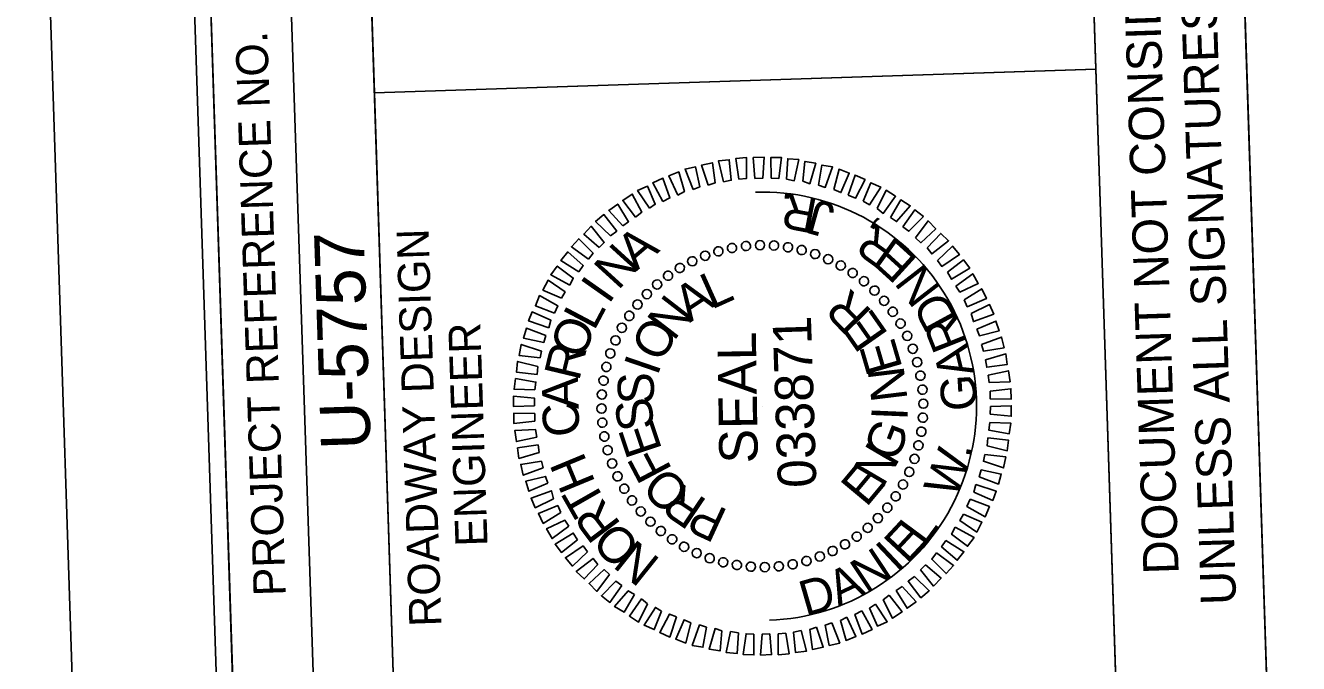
# Model space of a CAD drawing. Extents: x 1627314 to 1628469, y 762309 to 764230.
# Drawn here: x 1627314.2 to 1627512.6, y 763788.2 to 763887.6 of the extents above; entities that cross this region are included whole.
import ezdxf

# ---------------------------------------------------------------- set-up
doc = ezdxf.new("R2010")
doc.units = 0
for name, color, linetype in [('Old_Level_2', 7, 'Continuous'), ('Scratch_Level_0', 7, 'Continuous'), ('Sheet Data Field CELL', 7, 'Continuous'), ('Sheet Plot Border Inside CELL', 7, 'Continuous'), ('Sheet Plot Border Outside CELL', 7, 'Continuous'), ('Sheet Professional Seal CELL', 7, 'Continuous'), ('Sheet Profile CELL', 7, 'Continuous'), ('Sheet Profile Grid Major CELL', 7, 'Continuous'), ('Sheet Profile Grid Minor CELL', 7, 'Continuous'), ('Sheet Sticker Exception Certification CELL', 7, 'Continuous')]:
    doc.layers.add(name, color=color, linetype=linetype)

msp = doc.modelspace()

# ---------------------------------------------------------------- linework, layer by layer
at = {"layer": 'Old_Level_2'}
msp.add_lwpolyline([(1627507.79, 763781.61), (1627501.25, 763981.49), (1627565.16, 763983.58), (1627571.7, 763783.7)], close=True, dxfattribs=at)
at = {"layer": 'Scratch_Level_0'}
msp.add_arc((1627429.07, 763828.3), 33.36, 271.8735, 91.8735, dxfattribs=at)
at = {"layer": 'Sheet Plot Border Inside CELL'}
msp.add_lwpolyline([(1628446.34, 762357.53), (1628391.86, 764023.14), (1627337.33, 763988.65), (1627391.81, 762323.04)], close=True, dxfattribs=at)
at = {"layer": 'Sheet Plot Border Outside CELL'}
msp.add_lwpolyline([(1628469.21, 762345.27), (1628413.63, 764044.37), (1627314.22, 764008.4), (1627369.79, 762309.31)], close=True, dxfattribs=at)
at = {"layer": 'Sheet Professional Seal CELL'}
for p, q in [((1627422.18, 763852.44), (1627422.18, 763852.44)), ((1627424.36, 763852.91), (1627424.36, 763852.91)), ((1627426.5, 763853.28), (1627426.5, 763853.28)), ((1627428.7, 763853.4), (1627428.7, 763853.4)), ((1627430.9, 763853.32), (1627430.9, 763853.32)), ((1627433.06, 763853.04), (1627433.06, 763853.04)), ((1627435.18, 763852.66), (1627435.18, 763852.66)), ((1627418.13, 763850.9), (1627418.13, 763850.9)), ((1627420.1, 763851.77), (1627420.1, 763851.77)), ((1627437.3, 763852.03), (1627437.3, 763852.03)), ((1627439.33, 763851.2), (1627439.33, 763851.2)), ((1627441.31, 763850.26), (1627441.31, 763850.26)), ((1627414.35, 763848.63), (1627414.35, 763848.63)), ((1627416.21, 763849.84), (1627416.21, 763849.84)), ((1627443.15, 763849.07), (1627443.15, 763849.07)), ((1627412.64, 763847.32), (1627412.64, 763847.32)), ((1627444.94, 763847.78), (1627444.94, 763847.78)), ((1627446.54, 763846.33), (1627446.54, 763846.33)), ((1627411.04, 763845.77), (1627411.04, 763845.77)), ((1627448.09, 763844.73), (1627448.09, 763844.73)), ((1627408.3, 763842.38), (1627408.3, 763842.38)), ((1627409.59, 763844.17), (1627409.59, 763844.17)), ((1627449.4, 763843.02), (1627449.4, 763843.02)), ((1627407.11, 763840.54), (1627407.11, 763840.54)), ((1627450.61, 763841.16), (1627450.61, 763841.16)), ((1627406.17, 763838.56), (1627406.17, 763838.56)), ((1627451.67, 763839.25), (1627451.67, 763839.25)), ((1627405.34, 763836.53), (1627405.34, 763836.53)), ((1627452.54, 763837.27), (1627452.54, 763837.27)), ((1627404.71, 763834.41), (1627404.71, 763834.41)), ((1627453.21, 763835.19), (1627453.21, 763835.19)), ((1627453.68, 763833.01), (1627453.68, 763833.01)), ((1627404.33, 763832.29), (1627404.33, 763832.29)), ((1627454.05, 763830.87), (1627454.05, 763830.87)), ((1627404.05, 763830.13), (1627404.05, 763830.13)), ((1627454.17, 763828.67), (1627454.17, 763828.67)), ((1627403.97, 763827.93), (1627403.97, 763827.93)), ((1627429.07, 763828.3), (1627429.07, 763828.3)), ((1627454.09, 763826.47), (1627454.09, 763826.47)), ((1627404.09, 763825.73), (1627404.09, 763825.73)), ((1627404.46, 763823.59), (1627404.46, 763823.59)), ((1627453.81, 763824.31), (1627453.81, 763824.31)), ((1627404.93, 763821.41), (1627404.93, 763821.41)), ((1627453.43, 763822.19), (1627453.43, 763822.19)), ((1627405.6, 763819.33), (1627405.6, 763819.33)), ((1627452.8, 763820.07), (1627452.8, 763820.07)), ((1627406.47, 763817.36), (1627406.47, 763817.36)), ((1627451.97, 763818.04), (1627451.97, 763818.04)), ((1627407.53, 763815.44), (1627407.53, 763815.44)), ((1627451.03, 763816.06), (1627451.03, 763816.06)), ((1627408.74, 763813.58), (1627408.74, 763813.58)), ((1627449.84, 763814.22), (1627449.84, 763814.22)), ((1627410.05, 763811.87), (1627410.05, 763811.87)), ((1627447.1, 763810.83), (1627447.1, 763810.83)), ((1627448.55, 763812.43), (1627448.55, 763812.43)), ((1627411.6, 763810.27), (1627411.6, 763810.27)), ((1627413.2, 763808.82), (1627413.2, 763808.82)), ((1627445.5, 763809.28), (1627445.5, 763809.28)), ((1627414.99, 763807.53), (1627414.99, 763807.53)), ((1627441.93, 763806.76), (1627441.93, 763806.76)), ((1627443.79, 763807.97), (1627443.79, 763807.97)), ((1627416.83, 763806.34), (1627416.83, 763806.34)), ((1627418.81, 763805.4), (1627418.81, 763805.4)), ((1627438.04, 763804.83), (1627438.04, 763804.83)), ((1627440.01, 763805.7), (1627440.01, 763805.7)), ((1627420.84, 763804.57), (1627420.84, 763804.57)), ((1627422.96, 763803.94), (1627422.96, 763803.94)), ((1627425.08, 763803.56), (1627425.08, 763803.56)), ((1627427.24, 763803.28), (1627427.24, 763803.28)), ((1627429.44, 763803.2), (1627429.44, 763803.2)), ((1627431.64, 763803.32), (1627431.64, 763803.32)), ((1627433.78, 763803.69), (1627433.78, 763803.69)), ((1627435.96, 763804.16), (1627435.96, 763804.16))]:
    msp.add_line(p, q, dxfattribs=at)
for points in [[(1627420.64, 763862.74), (1627419.59, 763865.86), (1627421.28, 763866.22), (1627421.68, 763863.08)], [(1627423.02, 763863.27), (1627422.22, 763866.5), (1627423.91, 763866.7), (1627424.22, 763863.51)], [(1627425.41, 763863.65), (1627424.91, 763866.88), (1627426.6, 763867.04), (1627426.61, 763863.79)], [(1627427.91, 763863.78), (1627427.65, 763867.02), (1627429.35, 763867.08), (1627429.11, 763863.82)], [(1627430.41, 763863.81), (1627430.4, 763867.06), (1627432.06, 763867.02), (1627431.61, 763863.75)], [(1627432.82, 763863.64), (1627433.01, 763866.85), (1627434.72, 763866.71), (1627434.02, 763863.43)], [(1627435.38, 763863.33), (1627435.68, 763866.44), (1627437.39, 763866.14), (1627436.44, 763862.96)], [(1627415.89, 763861.19), (1627414.49, 763864.19), (1627416.02, 763864.79), (1627416.92, 763861.72)], [(1627418.26, 763862.07), (1627417.01, 763865.23), (1627418.65, 763865.58), (1627419.3, 763862.45)], [(1627437.8, 763862.75), (1627438.35, 763865.87), (1627440.01, 763865.58), (1627438.86, 763862.39)], [(1627440.22, 763862.08), (1627441.02, 763865.21), (1627442.59, 763864.61), (1627441.29, 763861.57)], [(1627442.45, 763861.16), (1627443.5, 763864.29), (1627445.07, 763863.59), (1627443.57, 763860.69)], [(1627411.45, 763859.14), (1627409.61, 763861.88), (1627411.14, 763862.58), (1627412.38, 763859.77)], [(1627413.57, 763860.21), (1627411.97, 763863.11), (1627413.55, 763863.81), (1627414.65, 763860.75)], [(1627444.78, 763860.23), (1627445.94, 763863.12), (1627447.51, 763862.42), (1627445.75, 763859.66)], [(1627409.3, 763857.77), (1627407.31, 763860.36), (1627408.78, 763861.35), (1627410.27, 763858.5)], [(1627446.97, 763859.1), (1627448.38, 763861.95), (1627449.81, 763861), (1627447.9, 763858.33)], [(1627449.02, 763857.67), (1627450.63, 763860.42), (1627452.11, 763859.52), (1627449.99, 763857.05)], [(1627407.29, 763856.4), (1627405.11, 763858.78), (1627406.53, 763859.78), (1627408.22, 763857.03)], [(1627450.97, 763856.23), (1627452.83, 763858.89), (1627454.17, 763857.84), (1627451.89, 763855.56)], [(1627403.65, 763853.03), (1627401.23, 763855.1), (1627402.39, 763856.34), (1627404.42, 763853.81)], [(1627405.39, 763854.84), (1627403.07, 763857.07), (1627404.38, 763858.16), (1627406.37, 763855.57)], [(1627452.92, 763854.54), (1627454.89, 763857.16), (1627456.08, 763855.95), (1627453.75, 763853.77)], [(1627401.96, 763851.18), (1627399.29, 763853.14), (1627400.45, 763854.38), (1627402.68, 763852.15)], [(1627454.73, 763852.95), (1627456.85, 763855.22), (1627458.09, 763854.06), (1627455.46, 763852.03)], [(1627400.47, 763849.23), (1627397.66, 763850.99), (1627398.72, 763852.32), (1627401.14, 763850.2)], [(1627456.34, 763851), (1627458.67, 763853.23), (1627459.76, 763851.92), (1627457.02, 763850.08)], [(1627457.9, 763849.15), (1627460.39, 763851.09), (1627461.38, 763849.82), (1627458.54, 763848.07)], [(1627399.04, 763847.13), (1627396.08, 763848.78), (1627397.09, 763850.12), (1627399.6, 763848.25)], [(1627459.22, 763847), (1627461.86, 763848.93), (1627462.71, 763847.41), (1627459.86, 763846.07)], [(1627397.75, 763845.14), (1627394.86, 763846.39), (1627395.66, 763847.92), (1627398.32, 763846.1)], [(1627460.49, 763844.89), (1627463.24, 763846.58), (1627463.99, 763845.05), (1627460.98, 763843.8)], [(1627396.68, 763842.8), (1627393.69, 763843.95), (1627394.34, 763845.52), (1627397.19, 763843.92)], [(1627395.8, 763840.52), (1627392.62, 763841.57), (1627393.17, 763842.98), (1627396.11, 763841.68)], [(1627461.62, 763842.72), (1627464.47, 763844.12), (1627465.12, 763842.64), (1627461.96, 763841.48)], [(1627394.98, 763838.24), (1627391.85, 763838.89), (1627392.3, 763840.45), (1627395.29, 763839.3)], [(1627462.5, 763840.3), (1627465.46, 763841.55), (1627465.96, 763840.01), (1627462.88, 763839.26)], [(1627463.22, 763837.92), (1627466.34, 763839.07), (1627466.74, 763837.39), (1627463.51, 763836.88)], [(1627394.41, 763835.82), (1627391.14, 763836.21), (1627391.49, 763837.93), (1627394.62, 763836.88)], [(1627463.85, 763835.54), (1627467.02, 763836.45), (1627467.23, 763834.8), (1627464.04, 763834.35)], [(1627393.94, 763833.25), (1627390.73, 763833.6), (1627390.92, 763835.26), (1627394.05, 763834.46)], [(1627393.62, 763830.84), (1627390.36, 763830.94), (1627390.61, 763832.6), (1627393.78, 763832.05)], [(1627464.23, 763833.15), (1627467.41, 763833.81), (1627467.67, 763832.11), (1627464.42, 763831.96)], [(1627464.56, 763830.66), (1627467.8, 763831.02), (1627467.81, 763829.37), (1627464.55, 763829.46)], [(1627393.55, 763828.34), (1627390.3, 763828.23), (1627390.3, 763829.88), (1627393.56, 763829.54)], [(1627393.58, 763825.94), (1627390.34, 763825.58), (1627390.33, 763827.23), (1627393.59, 763827.14)], [(1627464.59, 763828.26), (1627467.84, 763828.37), (1627467.84, 763826.72), (1627464.58, 763827.06)], [(1627393.91, 763823.45), (1627390.73, 763822.79), (1627390.47, 763824.49), (1627393.72, 763824.64)], [(1627464.52, 763825.76), (1627467.78, 763825.66), (1627467.53, 763824.01), (1627464.36, 763824.55)], [(1627464.2, 763823.35), (1627467.41, 763823), (1627467.22, 763821.34), (1627464.09, 763822.14)], [(1627394.29, 763821.06), (1627391.12, 763820.16), (1627390.91, 763821.8), (1627394.1, 763822.25)], [(1627463.73, 763820.78), (1627467, 763820.39), (1627466.65, 763818.67), (1627463.52, 763819.72)], [(1627394.92, 763818.68), (1627391.8, 763817.53), (1627391.4, 763819.21), (1627394.63, 763819.72)], [(1627395.64, 763816.3), (1627392.68, 763815.05), (1627392.18, 763816.59), (1627395.26, 763817.34)], [(1627463.16, 763818.36), (1627466.29, 763817.71), (1627465.84, 763816.15), (1627462.85, 763817.3)], [(1627396.52, 763813.88), (1627393.67, 763812.48), (1627393.02, 763813.96), (1627396.18, 763815.12)], [(1627462.34, 763816.08), (1627465.52, 763815.04), (1627464.97, 763813.62), (1627462.02, 763814.92)], [(1627397.65, 763811.71), (1627394.9, 763810.02), (1627394.15, 763811.55), (1627397.16, 763812.8)], [(1627461.46, 763813.8), (1627464.45, 763812.65), (1627463.8, 763811.08), (1627460.95, 763812.68)], [(1627460.39, 763811.47), (1627463.28, 763810.21), (1627462.48, 763808.68), (1627459.82, 763810.5)], [(1627398.92, 763809.6), (1627396.28, 763807.67), (1627395.43, 763809.19), (1627398.28, 763810.53)], [(1627459.1, 763809.47), (1627462.06, 763807.82), (1627461.05, 763806.48), (1627458.54, 763808.35)], [(1627400.24, 763807.45), (1627397.75, 763805.51), (1627396.76, 763806.78), (1627399.6, 763808.53)], [(1627457.67, 763807.37), (1627460.48, 763805.62), (1627459.42, 763804.28), (1627457, 763806.4)], [(1627401.8, 763805.6), (1627399.47, 763803.37), (1627398.38, 763804.68), (1627401.12, 763806.52)], [(1627456.18, 763805.42), (1627458.85, 763803.46), (1627457.69, 763802.22), (1627455.46, 763804.45)], [(1627403.41, 763803.65), (1627401.29, 763801.38), (1627400.05, 763802.54), (1627402.68, 763804.58)], [(1627405.22, 763802.06), (1627403.25, 763799.44), (1627402.06, 763800.65), (1627404.39, 763802.83)], [(1627454.49, 763803.57), (1627456.91, 763801.5), (1627455.75, 763800.26), (1627453.72, 763802.79)], [(1627407.17, 763800.37), (1627405.31, 763797.71), (1627403.97, 763798.76), (1627406.25, 763801.04)], [(1627452.75, 763801.76), (1627455.07, 763799.54), (1627453.76, 763798.44), (1627451.77, 763801.03)], [(1627409.12, 763798.93), (1627407.51, 763796.18), (1627406.03, 763797.08), (1627408.15, 763799.55)], [(1627448.84, 763798.83), (1627450.83, 763796.24), (1627449.36, 763795.25), (1627447.87, 763798.1)], [(1627450.85, 763800.2), (1627453.03, 763797.82), (1627451.61, 763796.82), (1627449.92, 763799.57)], [(1627411.17, 763797.5), (1627409.76, 763794.65), (1627408.33, 763795.6), (1627410.24, 763798.27)], [(1627413.36, 763796.37), (1627412.2, 763793.48), (1627410.63, 763794.18), (1627412.39, 763796.94)], [(1627446.69, 763797.46), (1627448.53, 763794.72), (1627447, 763794.02), (1627445.76, 763796.83)], [(1627415.69, 763795.45), (1627414.64, 763792.31), (1627413.07, 763793.01), (1627414.57, 763795.91)], [(1627417.92, 763794.52), (1627417.12, 763791.39), (1627415.55, 763791.99), (1627416.85, 763795.03)], [(1627442.25, 763795.41), (1627443.65, 763792.41), (1627442.12, 763791.81), (1627441.22, 763794.88)], [(1627444.57, 763796.39), (1627446.17, 763793.49), (1627444.59, 763792.79), (1627443.49, 763795.85)], [(1627420.34, 763793.85), (1627419.79, 763790.73), (1627418.13, 763791.02), (1627419.28, 763794.21)], [(1627422.76, 763793.28), (1627422.46, 763790.16), (1627420.75, 763790.46), (1627421.7, 763793.64)], [(1627425.32, 763792.96), (1627425.13, 763789.75), (1627423.42, 763789.9), (1627424.12, 763793.17)], [(1627427.73, 763792.79), (1627427.74, 763789.54), (1627426.08, 763789.58), (1627426.53, 763792.85)], [(1627430.23, 763792.82), (1627430.49, 763789.58), (1627428.79, 763789.52), (1627429.03, 763792.78)], [(1627432.73, 763792.95), (1627433.23, 763789.72), (1627431.54, 763789.56), (1627431.53, 763792.81)], [(1627435.12, 763793.33), (1627435.92, 763790.1), (1627434.23, 763789.9), (1627433.92, 763793.09)], [(1627437.5, 763793.86), (1627438.55, 763790.74), (1627436.86, 763790.39), (1627436.46, 763793.52)], [(1627439.88, 763794.54), (1627441.13, 763791.38), (1627439.49, 763791.02), (1627438.84, 763794.15)]]:
    msp.add_lwpolyline(points, close=True, dxfattribs=at)
for centre, major_axis in [((1627420.13, 763851.73), (-0.257, 0.673)), ((1627422.21, 763852.42), (-0.197, 0.693)), ((1627424.34, 763852.93), (-0.136, 0.707)), ((1627426.5, 763853.25), (-0.074, 0.716)), ((1627428.69, 763853.38), (-0.011, 0.72)), ((1627430.87, 763853.32), (0.052, 0.718)), ((1627433.05, 763853.06), (0.114, 0.711)), ((1627435.19, 763852.62), (0.176, 0.698)), ((1627437.29, 763852), (0.236, 0.68)), ((1627416.2, 763849.83), (-0.369, 0.618)), ((1627418.13, 763850.87), (-0.314, 0.648)), ((1627439.32, 763851.19), (0.294, 0.657)), ((1627441.28, 763850.21), (0.35, 0.629)), ((1627414.37, 763848.62), (-0.422, 0.583)), ((1627443.14, 763849.06), (0.404, 0.596)), ((1627444.9, 763847.76), (0.454, 0.559)), ((1627411.07, 763845.76), (-0.517, 0.501)), ((1627412.66, 763847.26), (-0.471, 0.544)), ((1627446.53, 763846.3), (0.501, 0.517)), ((1627409.61, 763844.13), (-0.559, 0.454)), ((1627448.03, 763844.71), (0.544, 0.471)), ((1627408.31, 763842.37), (-0.596, 0.404)), ((1627449.39, 763843), (0.583, 0.422)), ((1627407.16, 763840.51), (-0.629, 0.35)), ((1627450.6, 763841.17), (0.618, 0.369)), ((1627406.18, 763838.55), (-0.657, 0.294)), ((1627451.64, 763839.25), (0.648, 0.314)), ((1627405.37, 763836.52), (-0.68, 0.236)), ((1627452.5, 763837.24), (0.673, 0.257)), ((1627404.75, 763834.42), (-0.698, 0.176)), ((1627453.19, 763835.16), (0.693, 0.197)), ((1627404.31, 763832.28), (-0.711, 0.114)), ((1627453.7, 763833.03), (0.707, 0.136)), ((1627404.05, 763830.11), (-0.718, 0.052)), ((1627454.02, 763830.87), (0.716, 0.074)), ((1627403.99, 763827.92), (-0.72, -0.011)), ((1627454.15, 763828.68), (0.72, 0.011)), ((1627404.12, 763825.73), (-0.716, -0.074)), ((1627454.08, 763826.5), (0.718, -0.052)), ((1627453.83, 763824.32), (0.711, -0.114)), ((1627404.44, 763823.57), (-0.707, -0.136)), ((1627453.39, 763822.18), (0.698, -0.176)), ((1627404.95, 763821.44), (-0.693, -0.197)), ((1627452.77, 763820.08), (0.68, -0.236)), ((1627405.64, 763819.36), (-0.673, -0.257)), ((1627451.96, 763818.05), (0.657, -0.294)), ((1627406.5, 763817.36), (-0.648, -0.314)), ((1627450.98, 763816.09), (0.629, -0.35)), ((1627407.54, 763815.43), (-0.618, -0.369)), ((1627449.83, 763814.23), (0.596, -0.404)), ((1627408.75, 763813.6), (-0.583, -0.422)), ((1627410.11, 763811.89), (-0.544, -0.471)), ((1627448.53, 763812.47), (0.559, -0.454)), ((1627411.61, 763810.3), (-0.501, -0.517)), ((1627447.07, 763810.84), (0.517, -0.501)), ((1627413.24, 763808.84), (-0.454, -0.559)), ((1627443.77, 763807.98), (0.422, -0.583)), ((1627445.48, 763809.34), (0.471, -0.544)), ((1627415, 763807.54), (-0.404, -0.596)), ((1627416.86, 763806.39), (-0.35, -0.629)), ((1627441.94, 763806.77), (0.369, -0.618)), ((1627418.82, 763805.41), (-0.294, -0.657)), ((1627420.85, 763804.6), (-0.236, -0.68)), ((1627422.95, 763803.98), (-0.176, -0.698)), ((1627435.93, 763804.18), (0.197, -0.693)), ((1627438.01, 763804.87), (0.257, -0.673)), ((1627440.01, 763805.73), (0.314, -0.648)), ((1627425.09, 763803.54), (-0.114, -0.711)), ((1627427.27, 763803.29), (-0.052, -0.718)), ((1627429.45, 763803.22), (0.011, -0.72)), ((1627431.64, 763803.35), (0.074, -0.716)), ((1627433.8, 763803.67), (0.136, -0.707))]:
    msp.add_ellipse(centre, major_axis=major_axis, ratio=0.999708, dxfattribs=at)
at = {"layer": 'Sheet Profile CELL'}
for p, q in [((1627359.37, 763776.71), (1627352.83, 763976.65)), ((1627368.59, 763877.11), (1627480.98, 763880.79))]:
    msp.add_line(p, q, dxfattribs=at)
for points in [[(1627340.28, 763976.24), (1627389.32, 762477.04), (1628438.76, 762511.37), (1628389.72, 764010.57)], [(1627368.59, 763877.11), (1627365.32, 763977.06), (1627477.76, 763980.74), (1627481.03, 763880.79)], [(1627346.82, 763776.3), (1627340.28, 763976.24), (1627365.32, 763977.06), (1627371.86, 763777.12)], [(1627371.86, 763777.12), (1627368.59, 763877.11), (1627481.03, 763880.79), (1627484.3, 763780.79)]]:
    msp.add_lwpolyline(points, close=True, dxfattribs=at)
at = {"layer": 'Sheet Profile Grid Major CELL'}
msp.add_lwpolyline([(1627363.17, 763276.61), (1627361.53, 763326.59), (1627861.27, 763342.93), (1627859.63, 763392.91), (1627359.9, 763376.56), (1627358.26, 763426.53), (1627858, 763442.88), (1627856.36, 763492.85), (1627356.63, 763476.51), (1627354.99, 763526.48), (1627854.73, 763542.83), (1627853.09, 763592.8), (1627353.36, 763576.45), (1627351.73, 763626.43), (1627851.46, 763642.77), (1627849.82, 763692.75), (1627350.09, 763676.4), (1627348.46, 763726.37), (1627848.19, 763742.72), (1627846.55, 763792.69), (1627346.82, 763776.35), (1627345.96, 763802.63)], dxfattribs=at)
at = {"layer": 'Sheet Sticker Exception Certification CELL'}
for p, q in [((1627501.25, 763981.49), (1627507.79, 763781.56)), ((1627501.25, 763981.49), (1627507.79, 763781.56)), ((1627484.3, 763780.79), (1627477.76, 763980.72)), ((1627484.3, 763780.79), (1627477.76, 763980.72))]:
    msp.add_line(p, q, dxfattribs=at)

# ---------------------------------------------------------------- texts
at = {"layer": 'Sheet Data Field CELL'}
msp.add_text('U-5757', height=7.75, rotation=91.8735, dxfattribs=at).set_placement((1627368.04, 763821.64))
at = {"layer": 'Sheet Professional Seal CELL'}
for s, height, rotation, p in [('A', 5.64, 40.4906, (1627409.42, 763849.27)), ('N', 5.64, 47.6924, (1627406.57, 763846.22)), ('I', 5.64, 54.8936, (1627405.09, 763844.03)), ('L', 5.64, 24.2743, (1627421.13, 763843.3)), ('A', 5.64, 33.6337, (1627417.74, 763841.24)), ('R', 5.64, 134.3549, (1627446.35, 763842.97)), ('N', 5.64, 52.3501, (1627415.24, 763838.3)), ('L', 5.64, 62.0943, (1627402.83, 763839.9)), ('E', 5.64, 124.9976, (1627448.81, 763839.5)), ('O', 5.64, 69.2946, (1627401.12, 763835.44)), ('O', 5.64, 61.707, (1627413.35, 763834.89)), ('SEAL', 5.998, 90.8735, (1627428.36, 763819.42)), ('E', 5.64, 106.2852, (1627450.94, 763834.27)), ('R', 5.64, 76.4946, (1627400.48, 763832.07)), ('I', 5.64, 71.0631, (1627412.71, 763832.87)), ('A', 5.64, 90.8938, (1627400.42, 763827.86)), ('S', 5.64, 89.7739, (1627412.15, 763828.55)), ('N', 5.64, 96.9299, (1627451.7, 763829.34)), ('C', 5.64, 98.0933, (1627400.85, 763823.93)), ('S', 5.64, 99.1291, (1627412.32, 763824.95)), ('I', 5.64, 87.5747, (1627451.66, 763825.99)), ('E', 5.64, 108.4845, (1627413.48, 763821.54)), ('G', 5.64, 68.8637, (1627449.97, 763819.38)), ('N', 5.64, 59.5074, (1627447.85, 763815.51)), ('H', 5.64, 112.4929, (1627403.1, 763816.39)), ('F', 5.64, 117.8405, (1627415.09, 763818.39)), ('E', 5.64, 50.1504, (1627445.25, 763812.42)), ('O', 5.64, 136.5547, (1627418.14, 763815.19)), ('T', 5.64, 119.6932, (1627404.85, 763813.2)), ('R', 5.64, 145.9131, (1627420.65, 763813.52)), ('R', 5.64, 126.894, (1627407.16, 763809.87)), ('P', 5.64, 155.2724, (1627423.9, 763812.02)), ('O', 5.64, 134.0952, (1627410.37, 763806.53)), ('N', 5.64, 141.297, (1627413.35, 763804.32))]:
    msp.add_text(s, height=height, rotation=rotation, dxfattribs=at).set_placement(p)
at = {"layer": 'Sheet Profile CELL'}
for s, height, p in [('PROJECT REFERENCE NO.', 5.0001, (1627354.78, 763798.78)), ('ROADWAY DESIGN', 5.0001, (1627379.05, 763794.02)), ('ENGINEER', 5, (1627386.24, 763806.51))]:
    msp.add_text(s, height=height, rotation=91.8735, dxfattribs=at).set_placement(p)
at = {"layer": 'Sheet Profile Grid Minor CELL'}
for s, height, rotation, p in [('R', 5.5, 169.2275, (1627437.92, 763860.58)), ('.', 5.5, 176.154, (1627433.96, 763861.41)), ('J', 5.5, 164.359, (1627440.63, 763859.71)), ('R', 5.5, 144.2523, (1627450.72, 763853.82)), (',', 5.5, 151.1787, (1627447.49, 763856.25)), ('E', 5.5, 137.6693, (1627453.51, 763851.17)), ('N', 5.5, 127.7376, (1627457.08, 763846.62)), ('D', 5.5, 118.5929, (1627459.64, 763841.93)), ('R', 5.5, 111.6665, (1627461.06, 763838.14)), ('033871', 5.998, 91.8735, (1627437.5, 763815.67)), ('A', 5.5, 103.4807, (1627462.14, 763833.49)), ('G', 5.5, 93.549, (1627462.53, 763827.71)), ('W', 5.5, 68.7626, (1627459.2, 763813.73)), ('.', 5.5, 80.3687, (1627461.52, 763820.09)), ('E', 5.5, 46.9243, (1627451.62, 763803.57)), ('L', 5.5, 53.5073, (1627454.31, 763806.32)), ('I', 5.5, 43.4038, (1627450.06, 763802.23)), ('N', 5.5, 33.4721, (1627445.25, 763799)), ('A', 5.5, 25.2863, (1627440.91, 763797)), ('D', 5.5, 16.1417, (1627435.79, 763795.51))]:
    msp.add_text(s, height=height, rotation=rotation, dxfattribs=at).set_placement(p)
at = {"layer": 'Sheet Sticker Exception Certification CELL'}
for s, p in [('UNLESS ALL SIGNATURES COMPLETED', (1627502.91, 763797.41)), ('UNLESS ALL SIGNATURES COMPLETED', (1627502.91, 763797.41)), ('DOCUMENT NOT CONSIDERED FINAL', (1627493.95, 763802.19)), ('DOCUMENT NOT CONSIDERED FINAL', (1627493.95, 763802.19))]:
    msp.add_text(s, height=5.5, rotation=91.8735, dxfattribs=at).set_placement(p)

doc.saveas('drawing.dxf')
